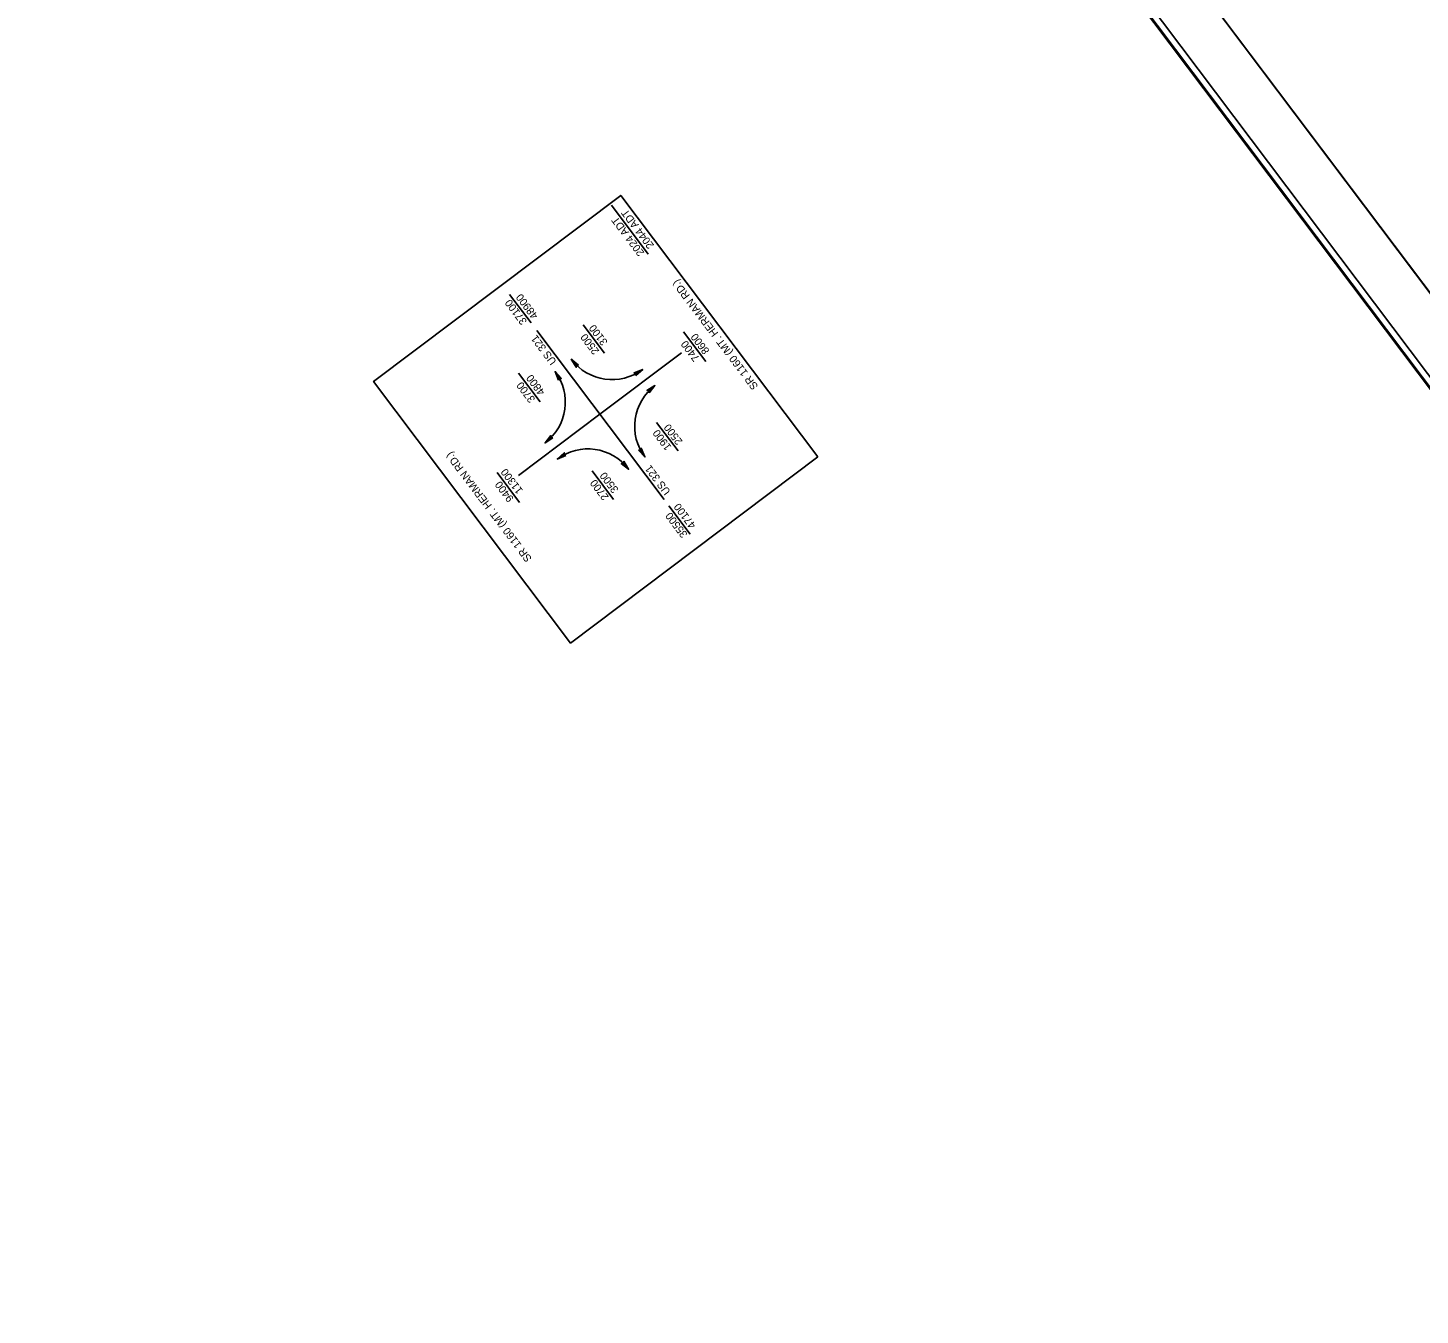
# Model space of a CAD drawing. Extents: x 1262337 to 1264328, y 775525 to 777528.
# Drawn here: x 1263223 to 1263776, y 776506 to 777017 of the extents above; entities that cross this region are included whole.
import ezdxf

# ---------------------------------------------------------------- set-up
doc = ezdxf.new("R2010")
doc.units = 0
for name, color, linetype in [('Prop PHM White Label Box', 7, 'Continuous'), ('Sheet Clip Boundary CELL', 7, 'Continuous'), ('Sheet Cutting Line CELL', 7, 'Continuous'), ('Sheet Layout Plan Border', 7, 'Continuous'), ('Sheet Plan CELL', 7, 'Continuous'), ('Sheet Plan Layout CELL', 7, 'Continuous'), ('Sheet Plot Border Inside CELL', 7, 'Continuous'), ('Sheet Plot Border Outside CELL', 7, 'Continuous'), ('Sheet Title CELL', 7, 'Continuous'), ('Sheet Title Data Points CELL', 7, 'Continuous')]:
    doc.layers.add(name, color=color, linetype=linetype)

msp = doc.modelspace()

# ---------------------------------------------------------------- linework, layer by layer
at = {"layer": 'Prop PHM White Label Box'}
msp.add_lwpolyline([(1263536.85, 776846.76), (1263458.64, 776950.59), (1263360.55, 776876.71), (1263438.76, 776772.87)], close=True, dxfattribs=at)
at = {"layer": 'Sheet Clip Boundary CELL'}
msp.add_lwpolyline([(1263888.49, 776271.07), (1264108.83, 776437.03), (1263657.31, 777036.5), (1263449.04, 777317.16), (1262881.72, 776889.85), (1262608.34, 776683.94), (1263270.12, 775805.31)], close=True, dxfattribs=at)
at = {"layer": 'Sheet Cutting Line CELL'}
msp.add_line((1264328.45, 776183.46), (1263315.59, 777528.19), dxfattribs=at)
at = {"layer": 'Sheet Layout Plan Border'}
msp.add_lwpolyline([(1264180.22, 776342.84), (1263337.92, 777461.13), (1262668.14, 776956.65), (1262782.01, 776805.47), (1262613.08, 776678.23), (1263341.52, 775711.12)], close=True, dxfattribs=at)
at = {"layer": 'Sheet Plan CELL'}
msp.add_lwpolyline([(1262469.12, 776869.36), (1263371.6, 775671.18), (1264210.31, 776302.91), (1263307.84, 777501.07)], close=True, dxfattribs=at)
at = {"layer": 'Sheet Plan Layout CELL'}
msp.add_lwpolyline([(1263371.64, 775671.18), (1264210.31, 776302.91), (1263307.85, 777501.06), (1262638.07, 776996.57), (1262782.01, 776805.47), (1262613.08, 776678.23)], close=True, dxfattribs=at)
at = {"layer": 'Sheet Plot Border Inside CELL'}
msp.add_lwpolyline([(1264304.66, 776181.82), (1263302.32, 777512.55), (1262459.63, 776877.83), (1263461.96, 775547.09)], close=True, dxfattribs=at)
at = {"layer": 'Sheet Plot Border Outside CELL'}
msp.add_lwpolyline([(1264328.45, 776183.46), (1263315.59, 777528.19), (1262440.94, 776869.39), (1263453.8, 775524.67)], close=True, dxfattribs=at)
at = {"layer": 'Sheet Title CELL'}
for p, q in [((1263469.56, 776927.3), (1263454.97, 776946.68)), ((1263423.08, 776899.99), (1263414.57, 776911.29)), ((1263475.91, 776829.85), (1263425.36, 776896.96)), ((1263452.24, 776887.92), (1263443.72, 776899.22)), ((1263492.47, 776884.66), (1263483.58, 776896.47)), ((1263482.71, 776888.02), (1263450.42, 776863.69)), ((1263426.63, 776868.63), (1263418.12, 776879.94)), ((1263418.13, 776839.37), (1263450.42, 776863.69)), ((1263481.43, 776849.17), (1263472.91, 776860.47)), ((1263418.48, 776828.7), (1263409.59, 776840.51)), ((1263455.82, 776829.88), (1263447.31, 776841.18)), ((1263477.76, 776827.4), (1263486.27, 776816.1))]:
    msp.add_line(p, q, dxfattribs=at)
for points in [[(1263441.93, 776883.19), (1263439.05, 776885.5), (1263440.99, 776882.33), (1263441.17, 776883.11)], [(1263434.02, 776877.23), (1263432.6, 776880.64), (1263435.11, 776877.9), (1263434.31, 776877.94)], [(1263464.63, 776879.04), (1263467.36, 776881.52), (1263463.93, 776880.1), (1263464.67, 776879.81)], [(1263431.75, 776854.27), (1263428.61, 776852.33), (1263430.92, 776855.24), (1263431, 776854.45)], [(1263465.76, 776849.48), (1263468.24, 776846.75), (1263466.82, 776850.18), (1263466.52, 776849.44)], [(1263459.85, 776845.03), (1263461.78, 776841.89), (1263458.88, 776844.2), (1263459.67, 776844.28)]]:
    msp.add_lwpolyline(points, close=True, dxfattribs=at)
for centre, start, end in [((1263455.2, 776897.67), 216.9874, 306.9874), ((1263416.45, 776868.48), 306.9874, 36.9874), ((1263484.39, 776858.91), 126.9874, 216.9874), ((1263445.64, 776829.72), 36.9874, 126.9874)]:
    msp.add_arc(centre, 20.21, start, end, dxfattribs=at)
at = {"layer": 'Sheet Title Data Points CELL'}
for points in [[(1263469.92, 776872.18), (1263472.23, 776875.06), (1263469.06, 776873.11), (1263469.84, 776872.94)], [(1263436.88, 776847.29), (1263433.48, 776845.87), (1263436.22, 776848.38), (1263436.17, 776847.58)]]:
    msp.add_lwpolyline(points, close=True, dxfattribs=at)

# ---------------------------------------------------------------- texts
at = {"layer": 'Sheet Title CELL'}
for s, height, p in [('2024 ADT', 3.032, (1263468.16, 776927.87)), ('2044 ADT', 3.032, (1263472.03, 776930.79)), ('SR 1160 (MT. HERMAN RD.)', 3.0322, (1263513.36, 776874.82)), ('37100', 3.032, (1263421.63, 776900.62)), ('48900', 3.032, (1263426.02, 776902.85)), ('US 321', 3.032, (1263433.35, 776884.66)), ('2500', 3.032, (1263450.28, 776888.8)), ('3100', 3.032, (1263453.63, 776892.4)), ('8600', 3.032, (1263494.04, 776888.91)), ('7400', 3.032, (1263490.12, 776886.05)), ('4800', 3.032, (1263428.75, 776872.58)), ('3700', 3.032, (1263424.88, 776869.67)), ('1900', 3.032, (1263478.95, 776850.73)), ('2500', 3.032, (1263483.34, 776852.96)), ('SR 1160 (MT. HERMAN RD.)', 3.0322, (1263423.53, 776806.45)), ('11300', 3.032, (1263420, 776833.45)), ('3500', 3.032, (1263457.94, 776833.83)), ('US 321', 3.032, (1263478.57, 776833.02)), ('9400', 3.032, (1263416.34, 776830.25)), ('2700', 3.032, (1263454.07, 776830.91)), ('35500', 3.032, (1263485.32, 776816.07)), ('47100', 3.032, (1263488.67, 776819.67))]:
    msp.add_text(s, height=height, rotation=126.9874, dxfattribs=at).set_placement(p)

doc.saveas('drawing.dxf')
